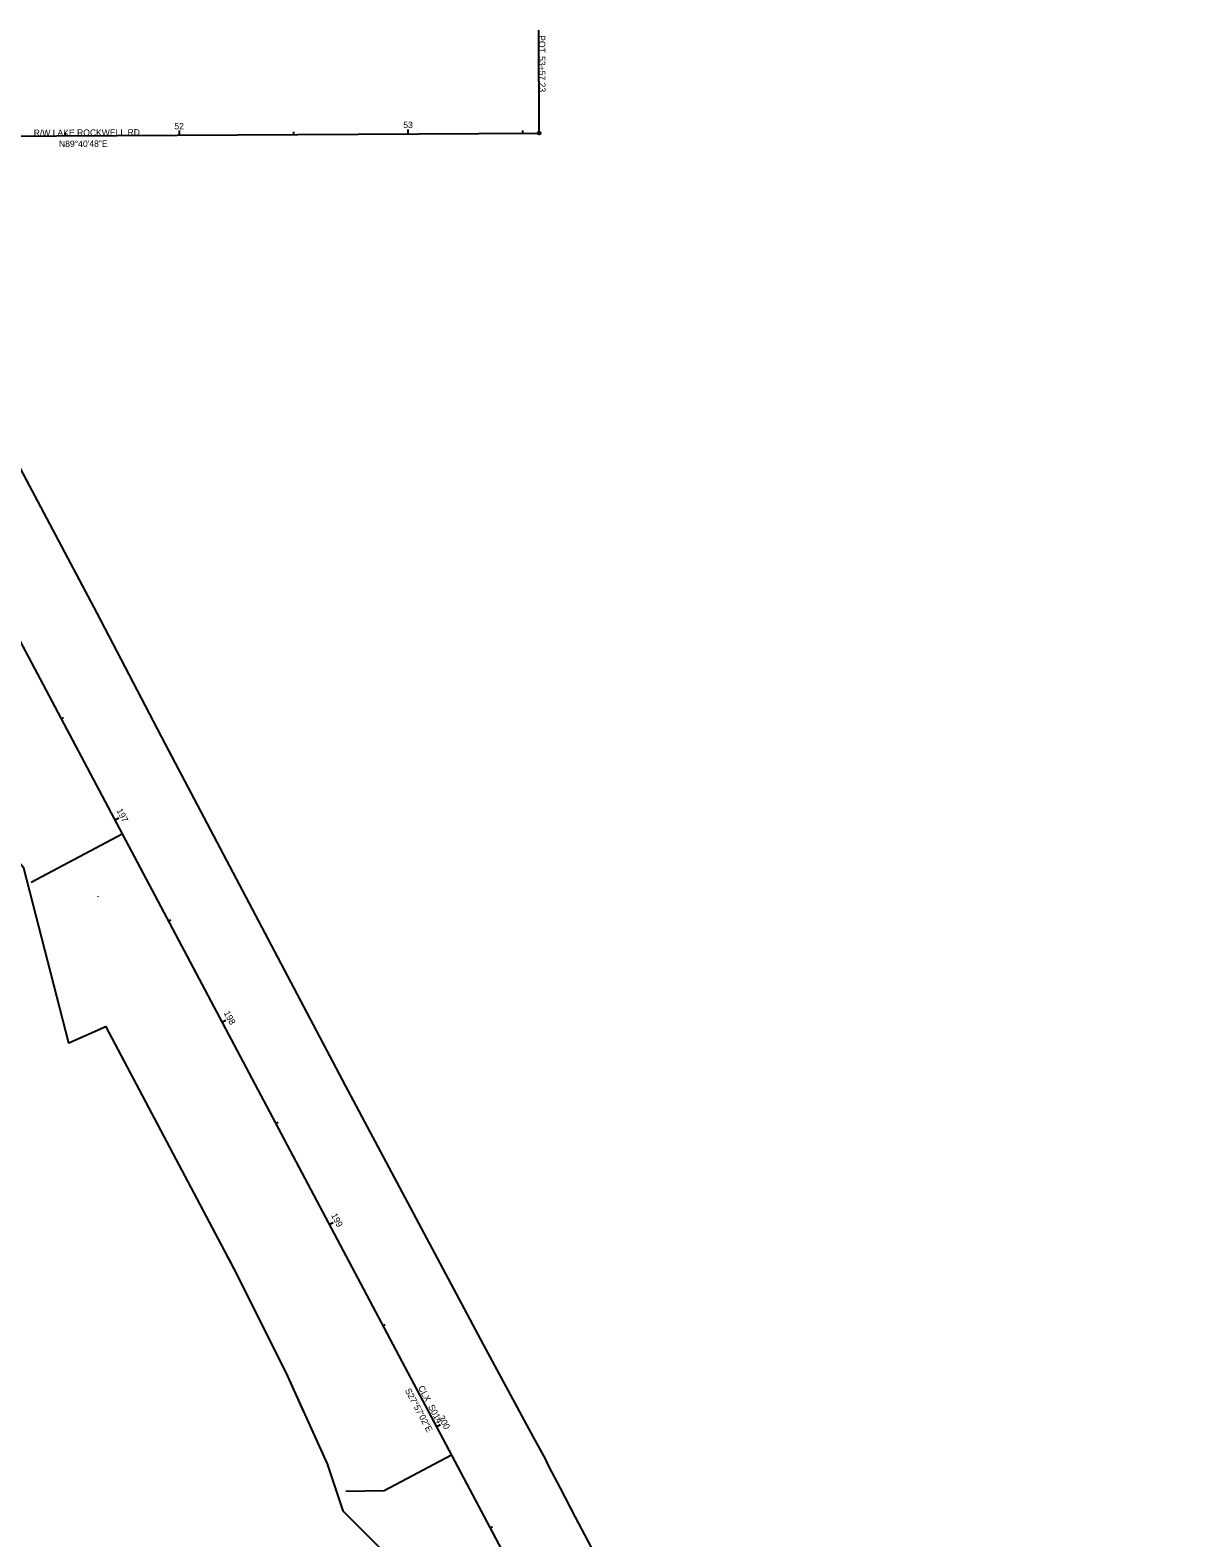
# Model space of a CAD drawing. Extents: x 2297881 to 2300632, y 559916 to 564460.
# Drawn here: x 2299521 to 2300022, y 561230 to 561889 of the extents above; entities that cross this region are included whole.
import ezdxf

# ---------------------------------------------------------------- set-up
doc = ezdxf.new("R2010")
doc.units = 0
for name, color, linetype in [('DT_P_Tie', 7, 'Continuous'), ('GE_P_Driveway_CL', 7, 'Continuous'), ('GE_X_Alignment', 7, 'Continuous'), ('GE_X_Alignment_1000_Bearings', 7, 'Continuous'), ('GE_X_Alignment_1000_Cardinal_Points', 7, 'Continuous'), ('GE_X_Alignment_1000_Distances', 7, 'Continuous'), ('GE_X_Alignment_1000_Stations', 7, 'Continuous'), ('GE_X_Alignment_100_Bearings', 7, 'Continuous'), ('GE_X_Alignment_100_Cardinal_Points', 7, 'Continuous'), ('GE_X_Alignment_100_Distances', 7, 'Continuous'), ('GE_X_Alignment_100_Stations', 7, 'Continuous'), ('GE_X_Alignment_500_Bearings', 7, 'Continuous'), ('GE_X_Alignment_500_Cardinal_Points', 7, 'Continuous'), ('GE_X_Alignment_500_Distances', 7, 'Continuous'), ('GE_X_Alignment_500_Stations', 7, 'Continuous')]:
    doc.layers.add(name, color=color, linetype=linetype)

msp = doc.modelspace()

# ---------------------------------------------------------------- linework, layer by layer
at = {"layer": 'DT_P_Tie'}
msp.add_line((2299606.22, 561354.55), (2299608.59, 561350.07), dxfattribs=at)
for points in [[(2300021.9, 560743.14), (2299904.11, 560965.53), (2299879.3, 561011.76), (2299790.8, 561178.6), (2299786, 561188.31), (2299759.1, 561239.25), (2299752.57, 561251.94), (2299747.43, 561261.55), (2299746.04, 561264.78), (2299740.79, 561274.25), (2299718.99, 561314.69), (2299658.76, 561427.53), (2299580.01, 561576.9), (2299550.09, 561634.04), (2299468.81, 561787.11), (2299475.78, 561803.22), (2299473.75, 561813.37)], [(2299554.13, 561453.58), (2299537.68, 561446.3), (2299518.01, 561522.65), (2299508.15, 561534.58)], [(2299553.83, 561453.42), (2299610.96, 561345.59), (2299633.24, 561300.88), (2299650.6, 561262.59)], [(2299606.22, 561354.55), (2299610.96, 561345.59), (2299633.24, 561300.88), (2299650.6, 561262.59)], [(2299606.22, 561354.55), (2299610.96, 561345.59), (2299633.24, 561300.88), (2299650.6, 561262.59)], [(2299606.22, 561354.55), (2299610.96, 561345.59), (2299633.24, 561300.88), (2299649.15, 561265.8)], [(2299606.22, 561354.55), (2299610.96, 561345.59), (2299633.24, 561300.88), (2299650.6, 561262.59)], [(2299606.22, 561354.55), (2299610.96, 561345.59), (2299633.24, 561300.88), (2299650.6, 561262.59)], [(2299606.22, 561354.55), (2299610.96, 561345.59), (2299633.24, 561300.88), (2299650.6, 561262.59)], [(2299606.22, 561354.55), (2299610.96, 561345.59), (2299633.24, 561300.88), (2299650.6, 561262.59)], [(2299606.22, 561354.55), (2299610.96, 561345.59), (2299633.24, 561300.88), (2299650.6, 561262.59)], [(2299606.22, 561354.55), (2299610.96, 561345.59), (2299615.97, 561335.54)], [(2299606.22, 561354.55), (2299610.96, 561345.59), (2299633.24, 561300.88), (2299640.32, 561285.25)], [(2299606.22, 561354.55), (2299610.96, 561345.59), (2299633.24, 561300.88), (2299650.6, 561262.59)], [(2299606.22, 561354.55), (2299610.96, 561345.59), (2299633.24, 561300.88), (2299650.6, 561262.59)], [(2299650.6, 561262.59), (2299657.52, 561242.08), (2299673.63, 561225.92)]]:
    msp.add_lwpolyline(points, dxfattribs=at)
at = {"layer": 'GE_P_Driveway_CL'}
for p, q in [((2299561.04, 561537.56), (2299521.29, 561516.47)), ((2299704.94, 561266.37), (2299675.52, 561250.77)), ((2299675.52, 561250.77), (2299658.82, 561250.49))]:
    msp.add_line(p, q, dxfattribs=at)
at = {"layer": 'GE_X_Alignment'}
for p, q in [((2299386.06, 561841.67), (2299743.29, 561843.67)), ((2299396.64, 561847.4), (2299991.21, 560726.85)), ((2299550.35, 561510.45), (2299550.39, 561510.39))]:
    msp.add_line(p, q, dxfattribs=at)
at = {"layer": 'GE_X_Alignment_1000_Cardinal_Points'}
msp.add_line((2299743.29, 561843.67), (2299743.03, 561888.67), dxfattribs=at)
msp.add_circle((2299743.29, 561843.67), 0.6, dxfattribs=at)
at = {"layer": 'GE_X_Alignment_1000_Stations'}
msp.add_line((2299698.37, 561278.74), (2299700.14, 561279.68), dxfattribs=at)
at = {"layer": 'GE_X_Alignment_100_Cardinal_Points'}
msp.add_line((2299743.29, 561843.67), (2299743.03, 561888.67), dxfattribs=at)
msp.add_circle((2299743.29, 561843.67), 0.6, dxfattribs=at)
at = {"layer": 'GE_X_Alignment_100_Stations'}
for p, q in [((2299536.06, 561842.51), (2299536.06, 561843.71)), ((2299586.06, 561842.79), (2299586.05, 561844.79)), ((2299636.06, 561843.07), (2299636.05, 561844.27)), ((2299686.06, 561843.35), (2299686.05, 561845.35)), ((2299736.06, 561843.63), (2299736.05, 561844.83)), ((2299534.33, 561587.91), (2299535.39, 561588.48)), ((2299557.76, 561543.75), (2299559.53, 561544.68)), ((2299581.2, 561499.58), (2299582.26, 561500.14)), ((2299604.63, 561455.41), (2299606.4, 561456.35)), ((2299628.07, 561411.24), (2299629.13, 561411.81)), ((2299651.5, 561367.08), (2299653.27, 561368.01)), ((2299674.94, 561322.91), (2299676, 561323.47)), ((2299698.37, 561278.74), (2299700.14, 561279.68)), ((2299721.81, 561234.57), (2299722.87, 561235.14))]:
    msp.add_line(p, q, dxfattribs=at)
at = {"layer": 'GE_X_Alignment_500_Cardinal_Points'}
msp.add_line((2299743.29, 561843.67), (2299743.03, 561888.67), dxfattribs=at)
msp.add_circle((2299743.29, 561843.67), 0.6, dxfattribs=at)
at = {"layer": 'GE_X_Alignment_500_Stations'}
for p, q in [((2299586.06, 561842.79), (2299586.06, 561843.99)), ((2299686.06, 561843.35), (2299686.05, 561844.55)), ((2299557.76, 561543.75), (2299558.82, 561544.31)), ((2299604.63, 561455.41), (2299605.69, 561455.97)), ((2299651.5, 561367.08), (2299652.56, 561367.64)), ((2299698.37, 561278.74), (2299700.14, 561279.68))]:
    msp.add_line(p, q, dxfattribs=at)

# ---------------------------------------------------------------- texts
at = {"layer": 'GE_X_Alignment_1000_Bearings'}
for s, rotation, p in [('N89°40\'48"E', 0.31995, (2299533.44, 561837.6)), ('S27°57\'02"E', 297.9505, (2299684.49, 561294.66))]:
    msp.add_text(s, height=2.8, rotation=rotation, dxfattribs=at).set_placement(p)
at = {"layer": 'GE_X_Alignment_1000_Cardinal_Points'}
for s, p in [('POT', (2299743.09, 561886.44)), ('53+57.23', (2299743.15, 561877.31))]:
    msp.add_text(s, height=2.8, rotation=270.31995, dxfattribs=at).set_placement(p)
at = {"layer": 'GE_X_Alignment_1000_Distances'}
for s, rotation, p in [(' R/W LAKE ROCKWELL RD', 0.31995, (2299521.34, 561842.38)), ('CLX_S014', 297.9505, (2299690.23, 561295.85))]:
    msp.add_text(s, height=2.8, rotation=rotation, dxfattribs=at).set_placement(p)
at = {"layer": 'GE_X_Alignment_1000_Stations'}
msp.add_text('200', height=2.8, rotation=297.9505, dxfattribs=at).set_placement((2299699.09, 561282.83))
at = {"layer": 'GE_X_Alignment_100_Bearings'}
for s, rotation, p in [('N89°40\'48"E', 0.31995, (2299533.44, 561837.6)), ('S27°57\'02"E', 297.9505, (2299684.49, 561294.66))]:
    msp.add_text(s, height=2.8, rotation=rotation, dxfattribs=at).set_placement(p)
at = {"layer": 'GE_X_Alignment_100_Cardinal_Points'}
for s, p in [('POT', (2299743.09, 561886.44)), ('53+57.23', (2299743.15, 561877.31))]:
    msp.add_text(s, height=2.8, rotation=270.31995, dxfattribs=at).set_placement(p)
at = {"layer": 'GE_X_Alignment_100_Distances'}
for s, rotation, p in [(' R/W LAKE ROCKWELL RD', 0.31995, (2299521.34, 561842.38)), ('CLX_S014', 297.9505, (2299690.23, 561295.85))]:
    msp.add_text(s, height=2.8, rotation=rotation, dxfattribs=at).set_placement(p)
at = {"layer": 'GE_X_Alignment_100_Stations'}
for s, rotation, p in [('52', 0.31995, (2299583.86, 561845.32)), ('53', 0.31995, (2299683.87, 561845.88)), ('197', 297.9505, (2299558.45, 561547.89)), ('198', 297.9505, (2299605.34, 561459.5)), ('199', 297.9505, (2299652.23, 561371.14)), ('200', 297.9505, (2299699.09, 561282.83))]:
    msp.add_text(s, height=2.8, rotation=rotation, dxfattribs=at).set_placement(p)
at = {"layer": 'GE_X_Alignment_500_Bearings'}
for s, rotation, p in [('N89°40\'48"E', 0.31995, (2299533.44, 561837.6)), ('S27°57\'02"E', 297.9505, (2299684.49, 561294.66))]:
    msp.add_text(s, height=2.8, rotation=rotation, dxfattribs=at).set_placement(p)
at = {"layer": 'GE_X_Alignment_500_Cardinal_Points'}
for s, p in [('POT', (2299743.09, 561886.44)), ('53+57.23', (2299743.15, 561877.31))]:
    msp.add_text(s, height=2.8, rotation=270.31995, dxfattribs=at).set_placement(p)
at = {"layer": 'GE_X_Alignment_500_Distances'}
for s, rotation, p in [(' R/W LAKE ROCKWELL RD', 0.31995, (2299521.34, 561842.38)), ('CLX_S014', 297.9505, (2299690.23, 561295.85))]:
    msp.add_text(s, height=2.8, rotation=rotation, dxfattribs=at).set_placement(p)
at = {"layer": 'GE_X_Alignment_500_Stations'}
msp.add_text('200', height=2.8, rotation=297.9505, dxfattribs=at).set_placement((2299699.09, 561282.83))

doc.saveas('drawing.dxf')
